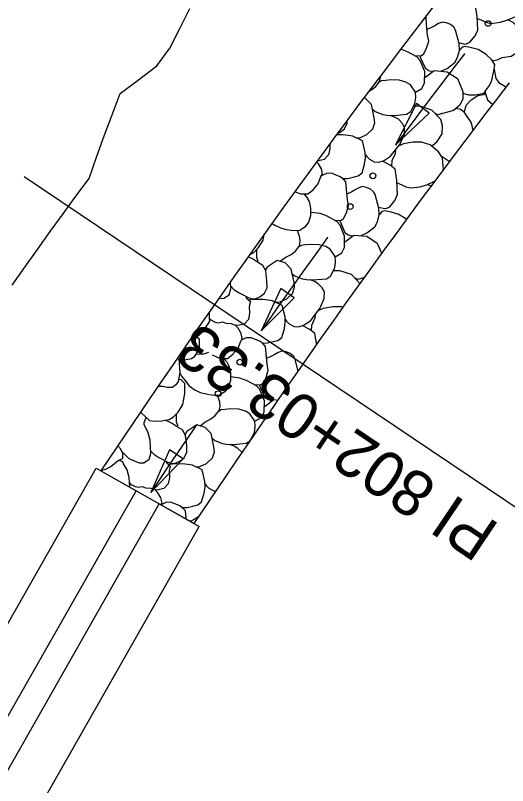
# Model space of a CAD drawing. Extents: x 1237212 to 1293764, y 379349 to 410301.
# Drawn here: x 1283498 to 1283562.5, y 404373.6 to 404474.6 of the extents above; entities that cross this region are included whole.
import ezdxf

# ---------------------------------------------------------------- set-up
doc = ezdxf.new("R2010")
doc.units = 0
for name, color, linetype in [('B-Sub-Pier Cap', 7, 'Continuous'), ('B-Tbl-Title Block', 7, 'Continuous'), ('B-Title Block (No Plot)', 7, 'Continuous'), ('R_Axis Annot', 7, 'Continuous'), ('R_Exist Surface', 7, 'Continuous'), ('R_Grid', 7, 'Continuous'), ('R_Horz Alg Annot', 7, 'Continuous'), ('R_Shld', 7, 'Continuous')]:
    doc.layers.add(name, color=color, linetype=linetype)

msp = doc.modelspace()

# ---------------------------------------------------------------- linework, layer by layer
at = {"layer": 'B-Sub-Pier Cap'}
msp.add_line((1283509.17, 404414.92), (1283521.39, 404407.98), dxfattribs=at)
for points in [[(1283553.27, 404476.44), (1283551.56, 404474.22), (1283549.85, 404472), (1283548.15, 404469.77), (1283546.46, 404467.54), (1283544.77, 404465.3), (1283543.09, 404463.06), (1283541.42, 404460.81), (1283539.75, 404458.56), (1283538.08, 404456.3), (1283536.43, 404454.04), (1283534.78, 404451.77), (1283533.13, 404449.5), (1283531.5, 404447.22), (1283529.87, 404444.94), (1283528.24, 404442.65), (1283526.62, 404440.36), (1283525.01, 404438.07), (1283523.41, 404435.77), (1283521.81, 404433.46), (1283520.21, 404431.16), (1283518.63, 404428.85), (1283517.04, 404426.53), (1283515.46, 404424.21), (1283509.17, 404414.92)], [(1283521.39, 404407.98), (1283525.58, 404414.19), (1283527.13, 404416.48), (1283528.69, 404418.76), (1283530.25, 404421.05), (1283531.82, 404423.33), (1283533.39, 404425.61), (1283534.97, 404427.88), (1283536.55, 404430.15), (1283538.14, 404432.41), (1283539.74, 404434.67), (1283541.34, 404436.92), (1283542.95, 404439.17), (1283544.56, 404441.41), (1283546.18, 404443.65), (1283547.81, 404445.89), (1283549.44, 404448.12), (1283551.08, 404450.34), (1283552.73, 404452.56), (1283554.38, 404454.78), (1283556.04, 404456.99), (1283557.7, 404459.2), (1283559.37, 404461.4), (1283561.05, 404463.6), (1283562.73, 404465.79)]]:
    msp.add_lwpolyline(points, dxfattribs=at)
at = {"layer": 'B-Tbl-Title Block'}
for radius, start in [(869.47, 134.75), (905.47, 138.45801)]:
    msp.add_arc((1284344.24, 403884.33), radius, start, 157.33333, dxfattribs=at)
at = {"layer": 'B-Title Block (No Plot)'}
msp.add_arc((1284344.24, 403884.33), 881.47, 134.75, 157.33333, dxfattribs=at)
msp.add_arc((1284344.24, 403884.33), 881.47, 134.75, 157.33333, dxfattribs=at)
at = {"layer": 'R_Axis Annot'}
for p, q in [((1283552.58, 404473.09), (1283551.93, 404472.77)), ((1283558.4, 404470.25), (1283558.41, 404470.19)), ((1283560.51, 404468.67), (1283561.25, 404468.86)), ((1283560.71, 404467.56), (1283560.94, 404466.36)), ((1283552.45, 404457.54), (1283552.68, 404457.61)), ((1283552.48, 404452.22), (1283551.98, 404452.46)), ((1283542.06, 404451.51), (1283541.41, 404451.19)), ((1283547.89, 404448.67), (1283547.9, 404448.61)), ((1283531.6, 404447.37), (1283532.03, 404447.06)), ((1283531.55, 404429.94), (1283530.9, 404429.62)), ((1283535.04, 404427.97), (1283534.96, 404428.28)), ((1283529.24, 404419.57), (1283529.12, 404419.57)), ((1283442.9, 404299.75), (1283508.57, 404415.27)), ((1283508.57, 404415.27), (1283513.78, 404412.3)), ((1283448.12, 404296.78), (1283513.78, 404412.3)), ((1283451.16, 404295.05), (1283516.82, 404410.57)), ((1283516.82, 404410.57), (1283522.04, 404407.61)), ((1283520.34, 404408.58), (1283520.33, 404408.71)), ((1283521.04, 404408.36), (1283520.86, 404408.28)), ((1283456.38, 404292.09), (1283522.04, 404407.61))]:
    msp.add_line(p, q, dxfattribs=at)
for points in [[(1283558.51, 404474.23), (1283559.12, 404474), (1283559.64, 404473.74), (1283560.29, 404473.58), (1283561.53, 404473.72), (1283562.5, 404474.04), (1283563.42, 404474.45), (1283563.73, 404474.54), (1283564.32, 404475.25), (1283564.58, 404476.07), (1283564.53, 404476.43), (1283564.46, 404477.52), (1283563.92, 404478.31), (1283562.85, 404479.21), (1283561.72, 404479.58), (1283560.62, 404479.58), (1283559.34, 404479.36), (1283558.65, 404479.03)], [(1283557.08, 404470.89), (1283557.55, 404471.11), (1283558.23, 404471.94), (1283558.59, 404472.71), (1283558.5, 404474.53), (1283558.25, 404476.04), (1283557.6, 404476.56), (1283556.66, 404477.07), (1283556.6, 404477.09)], [(1283551.87, 404473.43), (1283551.79, 404474.36), (1283551.72, 404474.43)], [(1283561.25, 404468.86), (1283561.77, 404469.12), (1283562.95, 404469.3), (1283563.58, 404469.67), (1283564.57, 404470.48), (1283565.15, 404470.74), (1283565.18, 404471.38), (1283564.91, 404471.96), (1283564.12, 404472.83), (1283563.21, 404473.68), (1283562.5, 404474.04)], [(1283550.35, 404469.33), (1283551.18, 404469.36), (1283551.5, 404469.58), (1283551.87, 404470.31), (1283552.15, 404471.26), (1283551.99, 404472.04), (1283551.87, 404473.43)], [(1283555.99, 404471.43), (1283555.65, 404472.7), (1283555.44, 404473.09), (1283555.01, 404473.43), (1283554.49, 404473.65), (1283553.94, 404473.76), (1283553.42, 404473.57), (1283552.93, 404473.26), (1283552.58, 404473.09)], [(1283553.72, 404467.31), (1283554.54, 404467.68), (1283555.61, 404468.5), (1283555.93, 404469.15), (1283556.16, 404470.04), (1283556.12, 404470.92), (1283555.99, 404471.43)], [(1283557.08, 404470.89), (1283556.91, 404470.82), (1283556.09, 404471.01)], [(1283550.4, 404464.55), (1283551.26, 404465.05), (1283551.61, 404465.77), (1283551.63, 404467.25), (1283551.04, 404468.72), (1283550.6, 404469.19), (1283549.36, 404469.85), (1283548.48, 404470.19)], [(1283560.44, 404466.29), (1283560.71, 404467.56), (1283560.81, 404468.15), (1283560.43, 404468.81), (1283559.67, 404469.5), (1283558.63, 404470.14), (1283557.57, 404470.44), (1283556.84, 404470.57), (1283556.48, 404470.43), (1283556.16, 404470.05)], [(1283550.97, 404469.35), (1283551.04, 404469.17), (1283551.68, 404467.74), (1283552.11, 404467.4), (1283552.67, 404467.26)], [(1283551.62, 404466.44), (1283551.78, 404466.58), (1283552.84, 404467.39), (1283554.54, 404467.23), (1283555.9, 404466.35), (1283556.63, 404464.66), (1283556.61, 404463.69), (1283556.2, 404462.87), (1283555.4, 404462.14), (1283553.35, 404461.59), (1283552.93, 404461.79)], [(1283544.33, 404464.71), (1283544.61, 404464.87), (1283545.19, 404465.3), (1283545.7, 404465.98), (1283545.83, 404466.5), (1283545.81, 404466.68)], [(1283544.78, 404462.32), (1283545.13, 404462.01), (1283546.13, 404461.64), (1283546.91, 404461.5), (1283548.03, 404461.55), (1283549.24, 404461.66), (1283549.78, 404462.02), (1283550.34, 404463.09), (1283550.44, 404463.86), (1283550.4, 404464.56), (1283549.74, 404465.54), (1283549.16, 404465.88), (1283548.28, 404466.13), (1283547.24, 404466.18), (1283546.47, 404466.11), (1283545.96, 404466.04), (1283545.56, 404465.79)], [(1283559.54, 404464.64), (1283559.71, 404464.89), (1283560.09, 404465.43), (1283560.35, 404466.01), (1283560.44, 404466.29)], [(1283560.94, 404466.36), (1283561.33, 404465.83), (1283562.26, 404465.28), (1283562.33, 404465.26)], [(1283542.61, 404458.59), (1283543.18, 404458.63), (1283544.05, 404459.01), (1283544.82, 404459.74), (1283545.07, 404460.55), (1283545.01, 404461.2), (1283544.65, 404462.94), (1283543.85, 404463.75), (1283543.66, 404463.81)], [(1283556.62, 404464.41), (1283557.36, 404464.22), (1283558.21, 404464.19), (1283559.4, 404464.42), (1283559.54, 404464.64)], [(1283556.77, 404461.94), (1283557.09, 404462.88), (1283557.7, 404463.55), (1283558.6, 404464.14), (1283559.6, 404464.28)], [(1283559.54, 404464.64), (1283559.53, 404464.49), (1283559.85, 404463.55), (1283560.56, 404462.95)], [(1283552.68, 404457.61), (1283553.25, 404458.08), (1283553.91, 404459.09), (1283553.96, 404460.14), (1283553.71, 404460.96), (1283552.54, 404462.2), (1283551.01, 404462.72), (1283550.15, 404462.72)], [(1283557.95, 404459.53), (1283557.74, 404460.56), (1283556.84, 404461.89), (1283556.3, 404462.29), (1283555.76, 404462.42), (1283555.68, 404462.39)], [(1283540.2, 404459.16), (1283540.53, 404459.3), (1283541.11, 404459.76), (1283541.46, 404460.48), (1283541.46, 404460.87)], [(1283543.84, 404456.36), (1283544.01, 404456.12), (1283544.37, 404455.77), (1283545, 404455.42), (1283545.56, 404455.38), (1283546.22, 404455.55), (1283547.14, 404456.16), (1283548.38, 404457.78), (1283548.97, 404459.05), (1283548.98, 404459.93), (1283548.69, 404460.47), (1283548.17, 404461), (1283547.67, 404461.29), (1283547.11, 404461.51)], [(1283540.83, 404453.23), (1283540.82, 404453.23), (1283541.52, 404453.25), (1283542.25, 404453.42), (1283542.89, 404453.59), (1283543.41, 404453.97), (1283543.73, 404455.13), (1283543.85, 404455.95), (1283543.83, 404456.66), (1283543.46, 404458.18), (1283542.2, 404458.79), (1283540.95, 404458.96), (1283540.04, 404458.95)], [(1283539.16, 404457.75), (1283539.18, 404457.16), (1283539.01, 404456.33), (1283538.45, 404455.72), (1283537.57, 404455.52), (1283537.52, 404455.53)], [(1283554, 404454.26), (1283554.07, 404454.49), (1283554.02, 404454.86), (1283553.95, 404455.95), (1283553.41, 404456.73), (1283552.33, 404457.64), (1283551.21, 404458.01), (1283550.1, 404458.01), (1283548.83, 404457.78), (1283548.13, 404457.46)], [(1283547.29, 404454.83), (1283547.34, 404455.6), (1283547.77, 404456.52), (1283547.84, 404457.07)], [(1283553.78, 404456.19), (1283554.84, 404455.52), (1283554.96, 404455.55)], [(1283538.02, 404453.48), (1283538.22, 404453.83), (1283538.07, 404454.5), (1283537.68, 404455.17), (1283537.44, 404455.42)], [(1283546.56, 404449.32), (1283547.03, 404449.54), (1283547.71, 404450.37), (1283548.07, 404451.14), (1283547.98, 404452.96), (1283547.74, 404454.47), (1283547.09, 404454.99), (1283546.15, 404455.49), (1283546.09, 404455.52)], [(1283541.36, 404451.86), (1283541.27, 404452.79), (1283540.96, 404453.14), (1283540.52, 404453.46), (1283539.38, 404453.93), (1283538.73, 404453.91), (1283538.1, 404453.61)], [(1283534.6, 404451.53), (1283534.84, 404451.4), (1283535.39, 404451.21), (1283536.28, 404451.21), (1283536.99, 404451.76), (1283537.67, 404452.55), (1283538.02, 404453.48)], [(1283548, 404452.66), (1283548.6, 404452.43), (1283549.13, 404452.16), (1283549.77, 404452.01), (1283551.01, 404452.15), (1283551.98, 404452.46), (1283552.9, 404452.88), (1283552.98, 404452.9)], [(1283539.84, 404447.75), (1283540.67, 404447.79), (1283540.98, 404448.01), (1283541.36, 404448.74), (1283541.63, 404449.68), (1283541.48, 404450.46), (1283541.36, 404451.86)], [(1283545.47, 404449.85), (1283545.14, 404451.13), (1283544.92, 404451.51), (1283544.5, 404451.85), (1283543.98, 404452.08), (1283543.43, 404452.18), (1283542.91, 404451.99), (1283542.42, 404451.69), (1283542.06, 404451.51)], [(1283535.79, 404451.21), (1283536.17, 404450.75), (1283536.47, 404450.23), (1283536.66, 404449.34), (1283536.66, 404448.33), (1283536.4, 404447.5), (1283535.92, 404446.86), (1283535.23, 404446.42), (1283534.39, 404446.36), (1283533.49, 404446.51), (1283532.75, 404446.71), (1283532.03, 404447.06)], [(1283543.21, 404445.74), (1283544.03, 404446.11), (1283545.09, 404446.92), (1283545.41, 404447.57), (1283545.64, 404448.47), (1283545.6, 404449.34), (1283545.47, 404449.85)], [(1283539.88, 404442.98), (1283540.74, 404443.48), (1283541.09, 404444.2), (1283541.12, 404445.67), (1283540.53, 404447.14), (1283540.09, 404447.62), (1283538.85, 404448.28), (1283537.92, 404448.64), (1283536.66, 404448.8)], [(1283546.57, 404449.32), (1283546.4, 404449.24), (1283545.58, 404449.44)], [(1283549.25, 404447.85), (1283549.16, 404447.93), (1283548.12, 404448.56), (1283547.06, 404448.87), (1283546.32, 404448.99), (1283545.96, 404448.85), (1283545.64, 404448.47)], [(1283540.46, 404447.78), (1283540.52, 404447.59), (1283541.16, 404446.17), (1283541.59, 404445.83), (1283542.15, 404445.68)], [(1283528.66, 404443.24), (1283529.2, 404443.54), (1283529.82, 404444.19), (1283530.44, 404445.16), (1283530.58, 404445.93)], [(1283532.68, 404442.38), (1283533.33, 404442.87), (1283534.1, 404443.29), (1283534.68, 404443.73), (1283535.19, 404444.41), (1283535.31, 404444.93), (1283535.27, 404445.48), (1283534.95, 404446.4)], [(1283541.11, 404444.87), (1283541.26, 404445), (1283542.33, 404445.82), (1283544.03, 404445.66), (1283545.38, 404444.78), (1283545.99, 404443.38)], [(1283534.26, 404440.74), (1283534.62, 404440.43), (1283535.62, 404440.06), (1283536.39, 404439.93), (1283537.52, 404439.98), (1283538.73, 404440.09), (1283539.27, 404440.45), (1283539.83, 404441.51), (1283539.92, 404442.29), (1283539.88, 404442.99), (1283539.22, 404443.97), (1283538.65, 404444.31), (1283537.77, 404444.55), (1283536.73, 404444.6), (1283535.96, 404444.54), (1283535.45, 404444.47), (1283535.05, 404444.22)], [(1283529.6, 404443.95), (1283529.56, 404443.81), (1283529.57, 404442.92), (1283529.75, 404442.38)], [(1283529.69, 404442.25), (1283529.04, 404442.7), (1283528.47, 404442.98)], [(1283527.64, 404438.06), (1283528.47, 404437.62), (1283528.88, 404437.48), (1283529.36, 404437.46), (1283530.01, 404437.72), (1283530.6, 404438.19), (1283530.95, 404438.91), (1283530.94, 404439.8), (1283530.78, 404441.11), (1283530.38, 404441.85), (1283529.69, 404442.25)], [(1283532.1, 404437.01), (1283532.67, 404437.06), (1283533.54, 404437.44), (1283534.3, 404438.16), (1283534.56, 404438.97), (1283534.5, 404439.62), (1283534.13, 404441.36), (1283533.34, 404442.18), (1283532.27, 404442.5), (1283530.98, 404441.63), (1283530.71, 404441.23)], [(1283543.15, 404439.44), (1283542.02, 404440.63), (1283540.5, 404441.15), (1283539.63, 404441.14)], [(1283524.64, 404437.53), (1283524.7, 404437.5), (1283525.3, 404437.53), (1283525.99, 404437.99), (1283526.21, 404438.77), (1283526.17, 404439.72)], [(1283533.32, 404434.79), (1283533.5, 404434.55), (1283533.86, 404434.2), (1283534.49, 404433.84), (1283535.05, 404433.8), (1283535.7, 404433.98), (1283536.63, 404434.58), (1283537.87, 404436.2), (1283538.46, 404437.48), (1283538.47, 404438.36), (1283538.18, 404438.89), (1283537.65, 404439.42), (1283537.16, 404439.71), (1283536.6, 404439.94)], [(1283543.73, 404440.25), (1283542.84, 404440.01), (1283542.42, 404440.22)], [(1283526.2, 404439.11), (1283526.62, 404438.67), (1283527.29, 404438.24), (1283527.64, 404438.06)], [(1283528.15, 404437.79), (1283528.28, 404437.54), (1283528.78, 404437.09), (1283528.63, 404436.45), (1283528.67, 404435.59), (1283528.5, 404434.76), (1283527.94, 404434.15), (1283527.06, 404433.95), (1283526.62, 404434.03), (1283526.28, 404434.16), (1283525.77, 404434.21)], [(1283530.32, 404431.65), (1283530.31, 404431.65), (1283531.01, 404431.67), (1283531.74, 404431.85), (1283532.38, 404432.01), (1283532.9, 404432.4), (1283533.22, 404433.56), (1283533.33, 404434.38), (1283533.32, 404435.08), (1283532.94, 404436.6), (1283531.68, 404437.21), (1283530.44, 404437.38), (1283529.09, 404437.37), (1283528.54, 404437.3)], [(1283523.15, 404434.03), (1283523.47, 404434.52), (1283523.43, 404434.89), (1283523.4, 404435.62), (1283523.37, 404435.72)], [(1283536.78, 404433.25), (1283536.83, 404434.02), (1283537.25, 404434.95), (1283537.33, 404435.49)], [(1283540.94, 404436.35), (1283540.69, 404436.43), (1283539.59, 404436.43), (1283538.31, 404436.21), (1283537.62, 404435.88)], [(1283523.43, 404434.89), (1283523.57, 404434.72), (1283524.17, 404434.4), (1283524.6, 404434.33), (1283525.13, 404434.43), (1283525.41, 404434.29), (1283525.77, 404434.21)], [(1283521.74, 404432.44), (1283522.6, 404433.19), (1283523.15, 404434.03)], [(1283527.5, 404431.91), (1283527.71, 404432.25), (1283527.55, 404432.93), (1283527.17, 404433.59), (1283526.79, 404434)], [(1283537.46, 404431.44), (1283537.22, 404432.89), (1283536.58, 404433.42), (1283535.63, 404433.92), (1283535.57, 404433.94)], [(1283521, 404432.29), (1283521.53, 404432.28), (1283521.74, 404432.44)], [(1283521.47, 404429.95), (1283521.86, 404430.55), (1283522.08, 404431.21), (1283522.08, 404432.11), (1283521.74, 404432.44)], [(1283523.78, 404430.12), (1283524.32, 404429.83), (1283524.87, 404429.63), (1283525.77, 404429.64), (1283526.48, 404430.18), (1283527.15, 404430.97), (1283527.5, 404431.91)], [(1283530.84, 404430.28), (1283530.76, 404431.21), (1283530.44, 404431.56), (1283530.01, 404431.89), (1283528.87, 404432.36), (1283528.21, 404432.33), (1283527.58, 404432.04)], [(1283523.28, 404430.43), (1283522.45, 404430.14), (1283521.62, 404430.18)], [(1283534.96, 404428.28), (1283534.62, 404429.55), (1283534.41, 404429.94), (1283533.99, 404430.28), (1283533.46, 404430.5), (1283532.91, 404430.61), (1283532.39, 404430.42), (1283531.9, 404430.11), (1283531.55, 404429.94)], [(1283519.37, 404429.59), (1283519.53, 404427.79), (1283519.31, 404426.62), (1283519.01, 404426.16), (1283518.56, 404425.81), (1283517.89, 404425.82), (1283517.31, 404425.98), (1283516.66, 404425.97)], [(1283519.18, 404429.65), (1283519.89, 404429.43), (1283521.07, 404429.63), (1283521.47, 404429.95)], [(1283525.28, 404429.64), (1283525.66, 404429.18), (1283525.96, 404428.66), (1283526.15, 404427.77), (1283526.15, 404426.76), (1283525.88, 404425.92), (1283525.41, 404425.28), (1283524.72, 404424.84), (1283523.87, 404424.79), (1283522.98, 404424.94), (1283522.24, 404425.13), (1283521.52, 404425.48)], [(1283529.32, 404426.18), (1283530.15, 404426.21), (1283530.47, 404426.43), (1283530.84, 404427.16), (1283531.12, 404428.11), (1283530.96, 404428.89), (1283530.84, 404430.28)], [(1283519.51, 404427.76), (1283519.73, 404427.32), (1283520.18, 404426.77), (1283520.48, 404426.38), (1283520.71, 404426.1), (1283521.03, 404425.83), (1283521.52, 404425.48)], [(1283514.41, 404422.66), (1283514.48, 404422.46), (1283515.56, 404421.49), (1283516.29, 404421.41), (1283517.15, 404421.44), (1283518.12, 404421.65), (1283518.69, 404421.97), (1283519.3, 404422.61), (1283519.93, 404423.59), (1283520.19, 404425.06), (1283520.17, 404426.36), (1283519.69, 404426.83), (1283519.35, 404426.86)], [(1283529.37, 404421.4), (1283530.23, 404421.9), (1283530.58, 404422.62), (1283530.61, 404424.1), (1283530.01, 404425.57), (1283529.57, 404426.05), (1283528.33, 404426.7), (1283527.4, 404427.06), (1283526.15, 404427.23)], [(1283529.94, 404426.2), (1283530.01, 404426.02), (1283530.65, 404424.59), (1283531.08, 404424.25), (1283531.64, 404424.11)], [(1283522.17, 404420.8), (1283522.81, 404421.29), (1283523.59, 404421.72), (1283524.16, 404422.15), (1283524.67, 404422.83), (1283524.8, 404423.36), (1283524.75, 404423.91), (1283524.44, 404424.82)], [(1283530.59, 404423.29), (1283530.75, 404423.43), (1283531.82, 404424.25), (1283532.41, 404424.19)], [(1283519.08, 404422.38), (1283519.05, 404422.24), (1283519.05, 404421.34), (1283519.24, 404420.81)], [(1283523.75, 404419.17), (1283524.1, 404418.86), (1283525.1, 404418.49), (1283525.88, 404418.35), (1283527, 404418.4), (1283528.22, 404418.51), (1283528.75, 404418.87), (1283529.31, 404419.94), (1283529.41, 404420.71), (1283529.37, 404421.41), (1283528.71, 404422.39), (1283528.13, 404422.73), (1283527.25, 404422.98), (1283526.22, 404423.03), (1283525.45, 404422.96), (1283524.93, 404422.89), (1283524.53, 404422.65)], [(1283511.96, 404417.4), (1283512.83, 404416.53), (1283514.19, 404415.93), (1283514.79, 404415.95), (1283515.48, 404416.41), (1283515.7, 404417.19), (1283515.62, 404418.91), (1283515.32, 404420.01), (1283514.85, 404420.94), (1283514.84, 404421.23), (1283515.09, 404421.91)], [(1283519.17, 404420.68), (1283518.53, 404421.12), (1283517.65, 404421.55)], [(1283521.67, 404420.89), (1283521.34, 404420.41), (1283519.78, 404418.11), (1283518.22, 404415.8), (1283516.67, 404413.49), (1283515.73, 404412.08), (1283515.73, 404412.08), (1283515.73, 404412.08)], [(1283517.13, 404416.48), (1283517.96, 404416.04), (1283518.37, 404415.91), (1283518.84, 404415.88), (1283519.5, 404416.15), (1283520.09, 404416.61), (1283520.44, 404417.33), (1283520.43, 404418.22), (1283520.26, 404419.53), (1283519.87, 404420.28), (1283519.17, 404420.68)], [(1283521.58, 404415.44), (1283522.15, 404415.48), (1283523.03, 404415.86), (1283523.79, 404416.59), (1283524.05, 404417.4), (1283523.98, 404418.05), (1283523.62, 404419.79), (1283522.82, 404420.6), (1283521.75, 404420.93), (1283520.46, 404420.06), (1283520.2, 404419.66)], [(1283527.68, 404417.29), (1283527.67, 404417.32), (1283527.14, 404417.85), (1283526.64, 404418.14), (1283526.09, 404418.36)], [(1283509.22, 404415), (1283509.83, 404415.1), (1283510.46, 404415.46), (1283511.46, 404416.27), (1283512.04, 404416.53), (1283512.07, 404417.17), (1283511.8, 404417.75), (1283511.39, 404418.2)], [(1283515.68, 404417.54), (1283516.11, 404417.1), (1283516.78, 404416.67), (1283517.13, 404416.48)], [(1283512.87, 404412.82), (1283512.95, 404412.95), (1283512.92, 404413.32), (1283512.89, 404414.04), (1283512.63, 404415.02), (1283512.15, 404415.83), (1283512.04, 404416.08), (1283511.5, 404416.31)], [(1283517.64, 404416.21), (1283517.77, 404415.96), (1283518.26, 404415.52), (1283518.12, 404414.88), (1283518.15, 404414.01), (1283517.98, 404413.19), (1283517.42, 404412.57), (1283516.55, 404412.38), (1283516.1, 404412.46), (1283515.77, 404412.59), (1283515.26, 404412.64)], [(1283519.8, 404410.08), (1283519.79, 404410.08), (1283520.5, 404410.1), (1283521.22, 404410.27), (1283521.86, 404410.44), (1283522.38, 404410.82), (1283522.7, 404411.98), (1283522.82, 404412.8), (1283522.8, 404413.51), (1283522.43, 404415.03), (1283521.17, 404415.64), (1283519.93, 404415.81), (1283518.57, 404415.79), (1283518.03, 404415.73)], [(1283512.92, 404413.32), (1283513.06, 404413.14), (1283513.65, 404412.83), (1283514.09, 404412.75), (1283514.61, 404412.85), (1283514.9, 404412.71), (1283515.26, 404412.64)], [(1283517.05, 404410.44), (1283517.19, 404410.68), (1283517.04, 404411.35), (1283516.65, 404412.02), (1283516.28, 404412.42)], [(1283522.81, 404413.21), (1283522.99, 404412.98), (1283523.34, 404412.62), (1283523.98, 404412.27), (1283524.27, 404412.25)], [(1283520.33, 404408.71), (1283520.25, 404409.64), (1283519.93, 404409.99), (1283519.5, 404410.32), (1283518.36, 404410.78), (1283517.7, 404410.76), (1283517.07, 404410.46)], [(1283522.01, 404408.89), (1283521.88, 404408.84), (1283521.39, 404408.54), (1283521.04, 404408.36)]]:
    msp.add_lwpolyline(points, dxfattribs=at)
at = {"layer": 'R_Exist Surface'}
msp.add_lwpolyline([(1283497.56, 404439.24), (1283499.2, 404441.59), (1283500.86, 404443.94), (1283502.53, 404446.27), (1283504.21, 404448.6), (1283505.91, 404450.92), (1283507.63, 404453.22), (1283508.62, 404456.02), (1283509.62, 404458.82), (1283510.64, 404461.6), (1283511.71, 404464.37), (1283514.1, 404466.2), (1283516.52, 404468.01), (1283518.22, 404470.33), (1283519.52, 404472.93), (1283520.83, 404475.53)], dxfattribs=at)
at = {"layer": 'R_Grid'}
msp.add_lwpolyline([(1283598.67, 404386.43), (1283499.14, 404453.46)], dxfattribs=at)
msp.add_lwpolyline([(1283598.67, 404386.43), (1283499.14, 404453.46)], dxfattribs=at)
at = {"layer": 'R_Horz Alg Annot'}
for p, q in [((1283550.53, 404463.07), (1283547.78, 404457.64)), ((1283550.53, 404463.07), (1283547.78, 404457.64)), ((1283552.22, 404461.8), (1283550.53, 404463.07)), ((1283552.22, 404461.8), (1283550.53, 404463.07)), ((1283547.78, 404457.64), (1283552.22, 404461.8)), ((1283547.78, 404457.64), (1283552.22, 404461.8)), ((1283532.78, 404438.8), (1283530.2, 404433.28)), ((1283532.78, 404438.8), (1283530.2, 404433.28)), ((1283534.51, 404437.58), (1283532.78, 404438.8)), ((1283534.51, 404437.58), (1283532.78, 404438.8)), ((1283530.2, 404433.28), (1283534.51, 404437.58)), ((1283530.2, 404433.28), (1283534.51, 404437.58)), ((1283518.18, 404417.66), (1283515.73, 404412.08)), ((1283519.94, 404416.49), (1283518.18, 404417.66)), ((1283515.73, 404412.08), (1283519.94, 404416.49))]:
    msp.add_line(p, q, dxfattribs=at)
for points in [[(1283556.83, 404469.6), (1283555.49, 404467.85), (1283553.8, 404465.64), (1283552.12, 404463.42), (1283550.45, 404461.2), (1283548.78, 404458.97), (1283547.78, 404457.63)], [(1283556.83, 404469.6), (1283555.49, 404467.85), (1283553.8, 404465.64), (1283552.12, 404463.42), (1283550.45, 404461.2), (1283548.78, 404458.97), (1283547.78, 404457.63)], [(1283556.85, 404469.63), (1283556.83, 404469.6)], [(1283556.85, 404469.63), (1283556.83, 404469.6)], [(1283538.89, 404445.51), (1283537.26, 404443.25), (1283535.64, 404440.98), (1283534.03, 404438.71), (1283532.42, 404436.44), (1283530.82, 404434.16), (1283530.2, 404433.28)], [(1283538.89, 404445.51), (1283537.26, 404443.25), (1283535.64, 404440.98), (1283534.03, 404438.71), (1283532.42, 404436.44), (1283530.82, 404434.16), (1283530.2, 404433.28)], [(1283538.91, 404445.54), (1283538.89, 404445.51), (1283538.89, 404445.51)], [(1283538.91, 404445.54), (1283538.89, 404445.51), (1283538.89, 404445.51)], [(1283521.69, 404420.93), (1283521.67, 404420.89)], [(1283521.69, 404420.93), (1283521.67, 404420.89)]]:
    msp.add_lwpolyline(points, dxfattribs=at)
for centre in [(1283559.93, 404473.55), (1283559.93, 404473.55), (1283544.83, 404453.59), (1283544.83, 404453.59), (1283541.86, 404449.55), (1283541.86, 404449.55), (1283527.38, 404429.15), (1283527.38, 404429.15), (1283524.53, 404425.02), (1283524.53, 404425.02)]:
    msp.add_circle(centre, 0.375, dxfattribs=at)
at = {"layer": 'R_Shld'}
for radius, start, end in [(913.47, 136.3373, 157.67823), (861.47, 134.75, 157.33333)]:
    msp.add_arc((1284344.24, 403884.33), radius, start, end, dxfattribs=at)

# ---------------------------------------------------------------- texts
at = {"layer": 'R_Grid'}
msp.add_text('PI 802+03.33', height=6, rotation=146.0417, dxfattribs=at).set_placement((1283561.64, 404407.75))
msp.add_text('PI 802+03.33', height=6, rotation=146.0417, dxfattribs=at).set_placement((1283561.64, 404407.75))

doc.saveas('drawing.dxf')
